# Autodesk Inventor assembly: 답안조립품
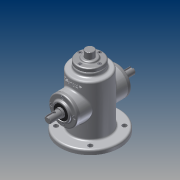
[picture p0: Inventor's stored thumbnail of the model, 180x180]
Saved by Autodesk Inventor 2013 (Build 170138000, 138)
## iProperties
Created: 2014-12
Part Number: 답안조립품
Document SubType Name: Assembly
Designer: H1
Author: H1
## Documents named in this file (13)
- C:\Users\H1\Desktop\441228V1012\답안조립품.iam
- C:\Users\H1\Desktop\441228V1012\본체.ipt
- C:\Users\H1\Desktop\441228V1012\M3x0.5x8.ipt
- M3x0.5.ipt
- C:\Users\H1\Desktop\441228V1012\베어링 6002.ipt
- 베어링 6002.ipt
- C:\Users\H1\Desktop\441228V1012\상단커버.ipt
- C:\Users\H1\Desktop\441228V1012\슬라이드.ipt
- C:\Users\H1\Desktop\441228V1012\오일실.ipt
- 오일실.ipt
- C:\Users\H1\Desktop\441228V1012\커버.ipt
- C:\Users\H1\Desktop\441228V1012\편심축.ipt
- C:\Users\H1\Desktop\441228V1012\커버_MIR.ipt
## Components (12 placed, 1 different names)
1. M3x0.5:2 — 각도:2
2. M3x0.5:3
3. M3x0.5:4
4. M3x0.5:5
5. M3x0.5:1 — 각도:3
6. M3x0.5:6
7. M3x0.5:7
8. M3x0.5:8
9. M3x0.5:9
10. M3x0.5:10
11. M3x0.5:11
12. M3x0.5:12
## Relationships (2: Angle 2)
- 각도:2 [Angle]: M3x0.5:2
- 각도:3 [Angle]: M3x0.5:1
